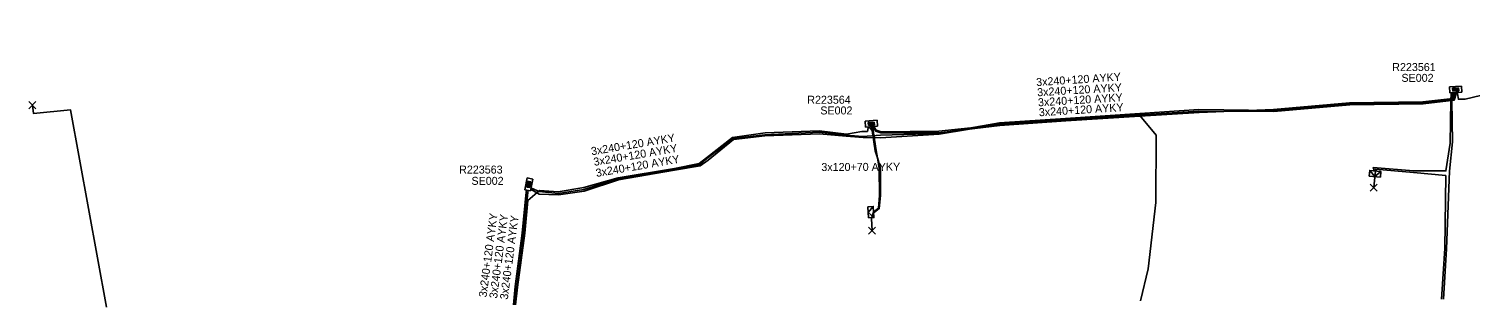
# Model space of a CAD drawing. Extents: x -536149 to -535465, y -1201639 to -1201298.
# Drawn here: x -535788.4 to -535608.3, y -1201639.3 to -1201604.5 of the extents above; entities that cross this region are included whole.
import ezdxf

# ---------------------------------------------------------------- set-up
doc = ezdxf.new("R2010")
doc.units = 0
for name, color, linetype in [('Vrstva 1', 7, 'Continuous'), ('Vrstva 28', 7, 'Continuous'), ('Vrstva 29', 7, 'Continuous'), ('Vrstva 30', 7, 'Continuous'), ('Vrstva 31', 7, 'Continuous'), ('Vrstva 34', 7, 'Continuous'), ('Vrstva 5', 7, 'Continuous'), ('Vrstva 52', 7, 'Continuous'), ('Vrstva 59', 7, 'Continuous'), ('Vrstva 6', 7, 'Continuous'), ('Vrstva 8', 7, 'Continuous'), ('Vrstva 9', 7, 'Continuous')]:
    doc.layers.add(name, color=color, linetype=linetype)

# ---------------------------------------------------------------- blocks, each defined once
blk = doc.blocks.new('NN800')
at = {"layer": 'Vrstva 1'}
for points in [[(-0.44, 0.44), (0.44, -0.44)], [(-0.44, -0.44), (0.44, 0.44)]]:
    blk.add_lwpolyline(points, dxfattribs=at)
blk = doc.blocks.new('NN620')
at = {"layer": 'Vrstva 8'}
for points in [[(0.75, 0), (-0.75, 0)], [(-0.75, 0), (-0.75, -0.75)], [(0.75, -0.75), (0.75, 0)], [(-0.75, -0.75), (0.75, -0.75)], [(0.37, -0.18), (-0.38, -0.18)], [(-0.38, -0.18), (-0.38, -0.56)], [(-0.38, -0.56), (0.37, -0.56)], [(0.32, -0.23), (-0.33, -0.23)], [(-0.33, -0.23), (-0.33, -0.51)], [(-0.33, -0.51), (0.32, -0.51)], [(0.27, -0.27), (-0.28, -0.27)], [(-0.28, -0.27), (-0.28, -0.46)], [(-0.28, -0.46), (0.27, -0.46)], [(0.23, -0.32), (-0.23, -0.32)], [(-0.23, -0.32), (-0.23, -0.42)], [(-0.23, -0.42), (0.23, -0.42)], [(-0.19, -0.37), (0.19, -0.37)], [(0.23, -0.42), (0.23, -0.32)], [(0.27, -0.46), (0.27, -0.27)], [(0.32, -0.51), (0.32, -0.23)], [(0.37, -0.56), (0.37, -0.18)]]:
    blk.add_lwpolyline(points, dxfattribs=at)
blk = doc.blocks.new('NN630')
at = {"layer": 'Vrstva 9'}
for points in [[(0, -0.7), (-0.7, 0)], [(-0.7, -0.7), (-0.7, 0), (0.7, 0), (0.7, -0.7)], [(-0.7, -0.7), (0.7, -0.7)], [(0, -0.7), (0.7, 0)]]:
    blk.add_lwpolyline(points, dxfattribs=at)

msp = doc.modelspace()

# ---------------------------------------------------------------- linework, layer by layer
at = {"layer": 'Vrstva 5'}
for points in [[(-535541.81, -1201609.57), (-535541.94, -1201609.6), (-535542.62, -1201609.63), (-535543.14, -1201608.42), (-535545.31, -1201608.81), (-535548.18, -1201607.57), (-535552.64, -1201605.64), (-535555.25, -1201604.46), (-535562.9, -1201604.76), (-535573.31, -1201605.57), (-535582.28, -1201606.62), (-535590.67, -1201607.71), (-535596.64, -1201608.7), (-535599.34, -1201609.92), (-535604.02, -1201612.44), (-535607.05, -1201612.79), (-535608.95, -1201613.25), (-535609.8, -1201613.28), (-535609.91, -1201612.61), (-535609.92, -1201612.45)], [(-535610.08, -1201612.45), (-535610.07, -1201612.6), (-535610.34, -1201613.4), (-535614.18, -1201613.86), (-535623.36, -1201613.97), (-535632.85, -1201614.82), (-535642.21, -1201614.77), (-535649.6, -1201615.22), (-535658.9, -1201615.78), (-535667.11, -1201616.38), (-535674.68, -1201617.65), (-535682.01, -1201618.09), (-535684.18, -1201618.08), (-535686.31, -1201617.89), (-535689.65, -1201617.62), (-535696.45, -1201617.87), (-535700.37, -1201618.3), (-535703.56, -1201620.91), (-535704.54, -1201621.62), (-535707.74, -1201622.17), (-535714.77, -1201623.38), (-535719.04, -1201624.78), (-535722.24, -1201625.22), (-535724.68, -1201625.16), (-535725.66, -1201624.59), (-535725.68, -1201624.58)], [(-535610.27, -1201612.46), (-535610.26, -1201612.67), (-535610.46, -1201613.23), (-535614.18, -1201613.73), (-535623.38, -1201613.85), (-535632.88, -1201614.7), (-535642.25, -1201614.58), (-535649.6, -1201615.08), (-535658.91, -1201615.69), (-535667.13, -1201616.21), (-535674.74, -1201617.55), (-535682.03, -1201617.77), (-535684.23, -1201617.92), (-535686.29, -1201617.78), (-535689.66, -1201617.41), (-535696.45, -1201617.73), (-535700.42, -1201618.17), (-535703.71, -1201620.71), (-535704.62, -1201621.46), (-535707.79, -1201622.06), (-535714.79, -1201623.24), (-535719.07, -1201624.56), (-535722.27, -1201625.06), (-535724.66, -1201624.84), (-535725.63, -1201624.42), (-535725.65, -1201624.42)], [(-535610.43, -1201612.47), (-535610.42, -1201612.64), (-535610.5, -1201613.18), (-535614.23, -1201613.59), (-535623.4, -1201613.71), (-535632.91, -1201614.58), (-535642.19, -1201614.92), (-535649.61, -1201615.41), (-535658.86, -1201615.98), (-535667.1, -1201616.55), (-535674.72, -1201617.47), (-535681.98, -1201617.47), (-535682.61, -1201617.28), (-535682.92, -1201616.82), (-535682.93, -1201616.72)], [(-535611.9, -1201638.28), (-535611.47, -1201631.97), (-535611.38, -1201622.83), (-535615.41, -1201622.44), (-535620.15, -1201622.02), (-535620.06, -1201622.25), (-535620.17, -1201622.26), (-535620.29, -1201622.22), (-535620.43, -1201621.8), (-535615.39, -1201622.24), (-535611.36, -1201622.25), (-535610.82, -1201618.78), (-535610.73, -1201613.48), (-535610.71, -1201612.6), (-535610.71, -1201612.48)], [(-535611.66, -1201638.28), (-535611.28, -1201631.98), (-535610.9, -1201622.29), (-535610.54, -1201618.61), (-535610.6, -1201613.48), (-535610.61, -1201612.61), (-535610.62, -1201612.48)], [(-535682.78, -1201616.71), (-535682.77, -1201616.8), (-535682.54, -1201617.15), (-535681.93, -1201617.35), (-535674.73, -1201617.27), (-535667.15, -1201616.48), (-535659.02, -1201615.9), (-535649.61, -1201615.33), (-535647.57, -1201617.76), (-535647.61, -1201626.21), (-535648.55, -1201634.5), (-535649.54, -1201638.49), (-535649.54, -1201638.51)], [(-535683.58, -1201616.76), (-535683.57, -1201616.86), (-535683.64, -1201617.31), (-535684.33, -1201617.33), (-535686.24, -1201617.64), (-535689.67, -1201617.23), (-535696.42, -1201617.5), (-535700.49, -1201618.05), (-535703.77, -1201620.61), (-535704.65, -1201621.31), (-535707.77, -1201621.94), (-535714.8, -1201623.1), (-535719.07, -1201624.31), (-535722.28, -1201624.86), (-535724.62, -1201624.71), (-535726.1, -1201625.97), (-535726.47, -1201630.03), (-535727.35, -1201636.79), (-535727.6, -1201638.99)], [(-535682.4, -1201620.62), (-535682.66, -1201619.72), (-535683.05, -1201617.18), (-535683.34, -1201616.84), (-535683.35, -1201616.75)], [(-535683.1, -1201616.73), (-535683.09, -1201616.83), (-535682.92, -1201617.21), (-535682.56, -1201619.71), (-535682.4, -1201620.62)], [(-535682.4, -1201620.62), (-535682.16, -1201621.96), (-535682.15, -1201625.31), (-535682.28, -1201626.91), (-535682.81, -1201627.34), (-535682.84, -1201627.34), (-535682.87, -1201627.39), (-535682.86, -1201627.46), (-535682.82, -1201627.46), (-535682.17, -1201626.96), (-535682.03, -1201625.32), (-535682.01, -1201621.95), (-535682.4, -1201620.62)], [(-535726.24, -1201624.67), (-535726.29, -1201624.9), (-535726.77, -1201630.03), (-535727.65, -1201636.73), (-535727.89, -1201638.99)], [(-535727.69, -1201638.99), (-535727.45, -1201636.75), (-535726.57, -1201630.05), (-535726.09, -1201624.92), (-535726.05, -1201624.71)]]:
    msp.add_lwpolyline(points, dxfattribs=at)
at = {"layer": 'Vrstva 52'}
msp.add_lwpolyline([(-535778.75, -1201639.3), (-535783.22, -1201614.61), (-535787.84, -1201615.08), (-535787.99, -1201614.02)], dxfattribs=at)
at = {"layer": 'Vrstva 59'}
for points in [[(-535620.17, -1201622.26), (-535620.24, -1201623.03), (-535620.37, -1201624.34)], [(-535682.87, -1201627.39), (-535683.15, -1201628.19), (-535683.06, -1201629.74)]]:
    msp.add_lwpolyline(points, dxfattribs=at)

# ---------------------------------------------------------------- block references
at = {"layer": 'Vrstva 28'}
for p, rotation in [((-535610.13, -1201612.43), -177.359833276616), ((-535683.13, -1201616.71), -176.14416383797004), ((-535725.59, -1201624.01), -101.44937775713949)]:
    msp.add_blockref('NN620', p, dxfattribs=dict(at, rotation=rotation))
at = {"layer": 'Vrstva 31'}
for p, rotation in [((-535620.17, -1201622.26), -5.564350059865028), ((-535682.87, -1201627.39), -86.57064722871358)]:
    msp.add_blockref('NN630', p, dxfattribs=dict(at, rotation=rotation))
at = {"layer": 'Vrstva 34', "rotation": 90}
for p in [(-535787.99, -1201614.02), (-535620.37, -1201624.34), (-535683.06, -1201629.74)]:
    msp.add_blockref('NN800', p, dxfattribs=at)

# ---------------------------------------------------------------- texts
at = {"layer": 'Vrstva 29'}
for s, p in [('R223561', (-535618.06, -1201609.75)), ('R223564', (-535691.16, -1201613.84)), ('R223563', (-535734.66, -1201622.58))]:
    msp.add_text(s, height=1, dxfattribs=at).set_placement(p)
at = {"layer": 'Vrstva 30'}
for p in [(-535616.91, -1201611.1), (-535689.53, -1201615.18), (-535733.12, -1201623.99)]:
    msp.add_text('SE002', height=1, dxfattribs=at).set_placement(p)
at = {"layer": 'Vrstva 6'}
for s, rotation, p in [('3x240+120 AYKY', 3.749, (-535662.52, -1201611.64)), ('3x240+120 AYKY', 3.446, (-535662.4, -1201612.91)), ('3x240+120 AYKY', 3.466, (-535662.3, -1201614.17)), ('3x240+120 AYKY', 3.526, (-535662.19, -1201615.41)), ('3x240+120 AYKY', 9.37, (-535718.09, -1201620.29)), ('3x240+120 AYKY', 9.568, (-535717.78, -1201621.62)), ('3x240+120 AYKY', 9.766, (-535717.5, -1201623.01)), ('3x120+70 AYKY', 0.171, (-535689.4, -1201622.26)), ('3x240+120 AYKY', 82.516, (-535731.24, -1201638.11)), ('3x240+120 AYKY', 82.519, (-535729.92, -1201638.25)), ('3x240+120 AYKY', 82.583, (-535728.59, -1201638.39))]:
    msp.add_text(s, height=1, rotation=rotation, dxfattribs=at).set_placement(p)

doc.saveas('drawing.dxf')
